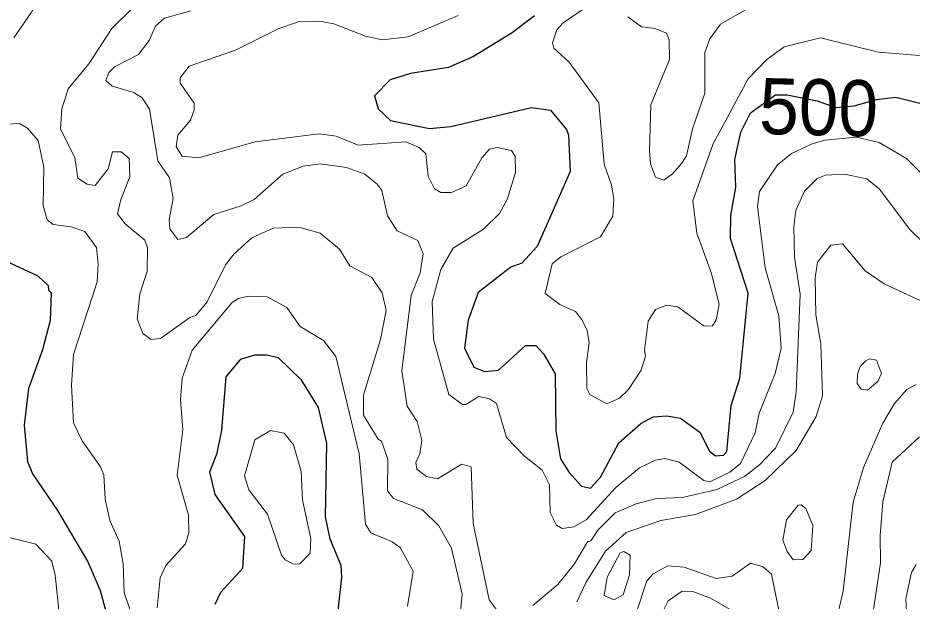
# Model space of a CAD drawing. Extents: x 763.2 to 816.8, y 7896.5 to 7952.7.
# Drawn here: x 772.72 to 775.277, y 7898.789 to 7900.455 of the extents above; entities that cross this region are included whole.
import ezdxf
from ezdxf.enums import TextEntityAlignment as Align

# ---------------------------------------------------------------- set-up
doc = ezdxf.new("R2010")
doc.units = 0
doc.header["$LTSCALE"] = 0.064
doc.layers.add('1', color=7, linetype='Continuous', lineweight=25)
doc.layers.add('2', color=7, linetype='Continuous', lineweight=13)
doc.layers.add('61', color=7, linetype='Continuous')

msp = doc.modelspace()

# ---------------------------------------------------------------- linework, layer by layer
at = {"layer": '1'}
for points in [[(774.1975, 7900.4606), (774.1333, 7900.4122), (774.0232, 7900.3441), (773.951, 7900.3128), (773.8425, 7900.2962), (773.7841, 7900.2783), (773.7397, 7900.2319), (773.7503, 7900.195), (773.7859, 7900.1619)], [(774.289, 7900.1358), (774.2944, 7900.1196), (774.2989, 7900.0156), (774.2047, 7899.8015), (774.1609, 7899.7545), (774.1299, 7899.7431), (774.0358, 7899.6704), (774.0074, 7899.5914), (773.9973, 7899.5108), (774.0238, 7899.4567), (774.0541, 7899.4448), (774.0939, 7899.4484), (774.1714, 7899.5187), (774.2007, 7899.5185), (774.2234, 7899.4946), (774.2565, 7899.4375), (774.2583, 7899.2748), (774.2716, 7899.1952), (774.2962, 7899.1558), (774.3316, 7899.1173), (774.3569, 7899.1117), (774.3862, 7899.1424), (774.4379, 7899.2409), (774.5017, 7899.2958), (774.5368, 7899.3151), (774.5755, 7899.3183), (774.6149, 7899.3116), (774.6702, 7899.2712), (774.6974, 7899.2169), (774.7145, 7899.2032), (774.7375, 7899.2057), (774.7474, 7899.216), (774.7597, 7899.347), (774.7843, 7899.426), (774.8086, 7899.6683), (774.7579, 7899.8246), (774.759, 7899.8902), (774.7726, 7899.9716), (774.7696, 7900.0505), (774.7873, 7900.1279), (774.8153, 7900.1838), (774.8864, 7900.2348), (774.9193, 7900.2352), (775.0053, 7900.218), (775.0593, 7900.1984), (775.111, 7900.2033), (775.1748, 7900.2217), (775.2301, 7900.2279), (775.2989, 7900.211)], [(773.7859, 7900.1619), (773.8968, 7900.1385), (773.9583, 7900.1446), (774.1884, 7900.1992), (774.2434, 7900.1908), (774.289, 7900.1358)], [(772.6827, 7899.7617), (772.7775, 7899.7176), (772.8064, 7899.6903), (772.8075, 7899.6768), (772.8153, 7899.6693), (772.8121, 7899.5904), (772.7904, 7899.5067)], [(772.7904, 7899.5067), (772.7508, 7899.3959), (772.7382, 7899.2912), (772.7477, 7899.187), (772.7616, 7899.1518), (772.8329, 7899.0479)], [(773.2838, 7898.7803), (773.3004, 7898.8142), (773.3628, 7898.883), (773.3686, 7898.9728), (773.284, 7899.0935), (773.2691, 7899.1578), (773.29, 7899.2109), (773.3033, 7899.2766), (773.3156, 7899.4291), (773.3578, 7899.4799), (773.3973, 7899.4926), (773.4309, 7899.4926), (773.4638, 7899.4844), (773.5286, 7899.4219), (773.5787, 7899.3413), (773.6024, 7899.2387), (773.5986, 7899.0296), (773.612, 7898.9667), (773.6437, 7898.891), (773.6452, 7898.8559), (773.6257, 7898.6775)], [(772.8329, 7899.0479), (772.9204, 7898.9009), (772.9555, 7898.8188), (772.9745, 7898.7488)]]:
    msp.add_lwpolyline(points, dxfattribs=at)
at = {"layer": '2'}
for points in [[(772.7002, 7900.9819), (772.7453, 7901.0131), (772.7791, 7901.0275), (772.8288, 7901.0213), (772.8725, 7900.9624), (772.876, 7900.916), (772.8666, 7900.84), (772.8238, 7900.6453), (772.8233, 7900.6037), (772.807, 7900.5593), (772.7594, 7900.471), (772.7082, 7900.3975)], [(774.4524, 7900.5896), (774.4245, 7900.5482), (774.3757, 7900.507), (774.2792, 7900.4404), (774.2608, 7900.4211), (774.2487, 7900.3836)], [(773.9856, 7898.7587), (773.9903, 7898.8087), (773.9602, 7898.9401), (773.9238, 7899.0033), (773.8774, 7899.0491), (773.7941, 7899.0815), (773.7769, 7899.104), (773.7783, 7899.1944), (773.7599, 7899.2459), (773.7505, 7899.2515), (773.7081, 7899.3197), (773.7079, 7899.3769), (773.7567, 7899.5364), (773.7733, 7899.6192), (773.7613, 7899.6697), (773.7324, 7899.7128), (773.6691, 7899.7468), (773.6398, 7899.7938), (773.5839, 7899.8394), (773.5237, 7899.8574), (773.4497, 7899.8538), (773.389, 7899.8261), (773.3384, 7899.7807), (773.3134, 7899.7489), (773.2615, 7899.6434), (773.2291, 7899.6044), (773.2112, 7899.599), (773.1279, 7899.5384), (773.1015, 7899.5356), (773.0772, 7899.5534), (773.0614, 7899.5948), (773.0685, 7899.6651), (773.0897, 7899.731), (773.091, 7899.798), (773.0827, 7899.82), (773.0263, 7899.8669), (773.0044, 7899.8948), (773.0142, 7899.9364), (773.0404, 7900.0005), (773.0386, 7900.0529), (773.0157, 7900.0724), (772.9901, 7900.0726), (772.9779, 7900.0235), (772.9414, 7899.9759), (772.9183, 7899.9794), (772.8914, 7899.9969), (772.8825, 7900.0563), (772.8417, 7900.1367), (772.8452, 7900.195), (772.8634, 7900.2517), (772.9226, 7900.3232), (772.9882, 7900.4242), (773.046, 7900.481)], [(773.2148, 7900.4753), (773.1397, 7900.454), (773.1139, 7900.4314), (773.0955, 7900.3902), (773.0645, 7900.35), (772.9967, 7900.3149), (772.9797, 7900.2988), (772.9716, 7900.2759), (772.9897, 7900.2601), (773.0513, 7900.2412), (773.0754, 7900.2264), (773.0961, 7900.1941), (773.12, 7900.0464), (773.1534, 7899.9977), (773.1636, 7899.9388), (773.1523, 7899.8788), (773.1541, 7899.8525), (773.1771, 7899.8218), (773.202, 7899.8272), (773.2801, 7899.8932), (773.358, 7899.9178), (773.3955, 7899.9362), (773.4777, 7900.0085), (773.5354, 7900.0313), (773.5843, 7900.0383), (773.6596, 7900.0272), (773.7116, 7900.0083), (773.7478, 7899.9801), (773.7605, 7899.9613), (773.7767, 7899.8894), (773.8048, 7899.8464), (773.864, 7899.8192), (773.8784, 7899.7809), (773.8699, 7899.7263), (773.8442, 7899.6619), (773.8179, 7899.4464), (773.8329, 7899.3459), (773.8618, 7899.3022), (773.875, 7899.2484), (773.8692, 7899.2097), (773.8576, 7899.1845)], [(774.1416, 7900.0601), (774.1312, 7900.0757), (774.0905, 7900.0841), (774.0686, 7900.0801), (774.0469, 7900.0552), (774.002, 7899.9747), (773.9601, 7899.9561), (773.9291, 7899.9563), (773.9113, 7899.9666), (773.893, 7900.0027), (773.8863, 7900.0665), (773.8675, 7900.0849), (773.8293, 7900.1006), (773.6928, 7900.0909), (773.6304, 7900.1166), (773.5813, 7900.1235), (773.3982, 7900.1004), (773.2377, 7900.0548), (773.1898, 7900.0596), (773.1722, 7900.0867), (773.1769, 7900.1196), (773.2139, 7900.1627), (773.2244, 7900.1918), (773.2239, 7900.2114), (773.1836, 7900.2681), (773.1841, 7900.2837), (773.2102, 7900.3171), (773.3426, 7900.3627), (773.464, 7900.4235), (773.5244, 7900.4442), (773.5821, 7900.4458), (773.6231, 7900.4381), (773.7139, 7900.4027), (773.7621, 7900.3919), (773.8364, 7900.401), (773.9786, 7900.4613)], [(774.799, 7900.477), (774.7291, 7900.4365), (774.6988, 7900.3948), (774.6842, 7900.3561), (774.6843, 7900.2394), (774.6493, 7900.1379), (774.6318, 7900.061), (774.6182, 7900.0401), (774.5921, 7900.0094), (774.5668, 7899.9915), (774.5428, 7900), (774.5291, 7900.0382), (774.5256, 7900.0751), (774.5295, 7900.2064), (774.5835, 7900.3358), (774.582, 7900.3924), (774.5743, 7900.4116), (774.5425, 7900.4243), (774.5036, 7900.4296), (774.4639, 7900.4581)], [(774.2487, 7900.3836), (774.2522, 7900.3687), (774.2968, 7900.3281), (774.3813, 7900.2123), (774.3964, 7900.0373), (774.4177, 7899.9774), (774.4242, 7899.9387), (774.4209, 7899.8888), (774.386, 7899.8294), (774.2726, 7899.7726), (774.2475, 7899.7524), (774.2275, 7899.6676), (774.2694, 7899.6361), (774.314, 7899.6156), (774.3328, 7899.5932), (774.3481, 7899.5613), (774.3536, 7899.5266), (774.3455, 7899.4712), (774.3472, 7899.3963), (774.3559, 7899.3791), (774.404, 7899.3523), (774.4405, 7899.368), (774.4661, 7899.3936), (774.5025, 7899.4485), (774.5147, 7899.4882), (774.5117, 7899.5049), (774.5219, 7899.5884), (774.5428, 7899.6221), (774.5756, 7899.6338), (774.6066, 7899.6292), (774.6823, 7899.5743), (774.7066, 7899.5753), (774.7168, 7899.5922), (774.7249, 7899.6356), (774.7033, 7899.725), (774.6615, 7899.8399), (774.6497, 7899.932), (774.7073, 7900.0931), (774.8078, 7900.2804), (774.8618, 7900.3361), (774.9108, 7900.3717), (775.0148, 7900.3977), (775.1804, 7900.3572), (775.2979, 7900.3472)], [(772.6672, 7900.1503), (772.7248, 7900.153), (772.7479, 7900.14), (772.7776, 7900.1048), (772.7941, 7900.0286)], [(775.3833, 7899.9315), (775.2608, 7900.053), (775.1831, 7900.0984), (775.1178, 7900.1138), (775.0273, 7900.1057), (774.9908, 7900.0954), (774.9324, 7900.067), (774.8916, 7900.0354), (774.8402, 7899.9585), (774.8353, 7899.9159), (774.8566, 7899.7408), (774.8958, 7899.6034), (774.9025, 7899.5114), (774.8853, 7899.4392), (774.8399, 7899.3259), (774.8285, 7899.2698), (774.7862, 7899.1814), (774.7554, 7899.1573), (774.699, 7899.1297), (774.681, 7899.1329), (774.6109, 7899.1856), (774.5696, 7899.1965), (774.5433, 7899.1917), (774.4974, 7899.1695), (774.4298, 7899.1134), (774.3454, 7899.021), (774.31, 7899.0009), (774.276, 7898.9964), (774.2605, 7899.0056), (774.2421, 7899.0414), (774.2404, 7899.1205), (774.2187, 7899.1624), (774.1684, 7899.2029), (774.1172, 7899.2562), (774.0883, 7899.353), (774.0687, 7899.3661), (774.0381, 7899.3727), (774.0008, 7899.3501), (773.9909, 7899.35), (773.952, 7899.3785), (773.9084, 7899.5371), (773.905, 7899.6446), (773.9291, 7899.7361), (773.9648, 7899.7966)], [(773.9648, 7899.7966), (774.0517, 7899.8517), (774.0971, 7899.8958), (774.1191, 7899.9361), (774.143, 7900.013), (774.1416, 7900.0601)], [(772.7941, 7900.0286), (772.7924, 7899.9189), (772.8037, 7899.8777), (772.8206, 7899.8643), (772.8723, 7899.8575), (772.9118, 7899.8445)], [(774.1929, 7898.7758), (774.2636, 7898.8357), (774.3113, 7898.8949), (774.3492, 7898.9581), (774.3586, 7898.9609), (774.3792, 7898.9924), (774.4276, 7899.0405), (774.4883, 7899.0669), (774.546, 7899.0816), (774.6208, 7899.085), (774.7184, 7899.1074), (774.7978, 7899.1448), (774.841, 7899.1781), (774.8864, 7899.2254), (774.9365, 7899.3286), (774.9451, 7899.3852), (774.9565, 7899.6652), (774.9404, 7899.7716), (774.9387, 7899.8584), (774.9448, 7899.9041), (774.9692, 7899.9598), (775.0051, 7899.9957), (775.0292, 7900.0052), (775.0832, 7900.0087), (775.1476, 7899.9952), (775.1835, 7899.9659), (775.2708, 7899.8505), (775.305, 7899.8165)], [(772.9118, 7899.8445), (772.9451, 7899.799), (772.9499, 7899.7513), (772.9466, 7899.7005), (772.8795, 7899.4935), (772.873, 7899.4055), (772.8795, 7899.2982), (772.9041, 7899.2467), (772.9563, 7899.1727), (772.9662, 7899.1495), (772.9699, 7899.0802), (772.9833, 7899.0186), (773.0098, 7898.9597), (773.0208, 7898.8954), (773.0243, 7898.8132), (773.0426, 7898.7573)], [(775.3021, 7899.6464), (775.1968, 7899.6948), (775.143, 7899.7321), (775.0782, 7899.8095), (775.0449, 7899.8059), (775.0063, 7899.757), (774.9996, 7899.7119), (775.0016, 7899.6063), (775.0159, 7899.5232), (775.0206, 7899.3753), (775.0023, 7899.3161), (774.9452, 7899.219), (774.8569, 7899.1334)], [(773.1179, 7898.7692), (773.1266, 7898.8547), (773.1434, 7898.8905), (773.1997, 7898.9522), (773.2086, 7898.9837), (773.208, 7899.034), (773.1755, 7899.1485), (773.1917, 7899.278), (773.1853, 7899.3646), (773.1894, 7899.426), (773.2186, 7899.506), (773.3318, 7899.6404), (773.3495, 7899.6533), (773.3793, 7899.6601), (773.4328, 7899.6582), (773.489, 7899.6273), (773.5269, 7899.5732), (773.5938, 7899.5327), (773.6291, 7899.4871), (773.696, 7899.209), (773.7136, 7899.008), (773.7295, 7898.9833), (773.7899, 7898.9583), (773.8135, 7898.9414), (773.8506, 7898.8746), (773.8341, 7898.7739)], [(775.0585, 7898.7268), (775.08, 7898.8178), (775.1082, 7899.0709), (775.1375, 7899.1706), (775.1936, 7899.297), (775.2268, 7899.3535), (775.2617, 7899.3931), (775.2883, 7899.407)], [(775.298, 7899.2576), (775.22, 7899.1852), (775.1929, 7899.0725), (775.1853, 7898.9764), (775.1867, 7898.898), (775.1623, 7898.739)], [(773.8576, 7899.1845), (773.861, 7899.1658), (773.8886, 7899.1443), (773.92, 7899.1377), (773.9899, 7899.1798), (774.0164, 7899.1719)], [(774.0164, 7899.1719), (774.0214, 7899.01), (774.0672, 7898.7921), (774.0908, 7898.7618)], [(774.8569, 7899.1334), (774.7748, 7899.0794), (774.6577, 7899.0358), (774.5584, 7899.019), (774.4589, 7898.9847), (774.4005, 7898.9317)], [(772.5945, 7898.5687), (772.7371, 7898.5429), (772.777, 7898.52), (772.8169, 7898.5134), (772.8693, 7898.5445), (772.8827, 7898.5848), (772.8859, 7898.6298), (772.8655, 7898.6964), (772.8387, 7898.7442), (772.8265, 7898.8624), (772.8167, 7898.9023), (772.7714, 7898.9516), (772.6948, 7898.9702)], [(774.4005, 7898.9317), (774.3452, 7898.8428), (774.3183, 7898.7864)], [(774.488, 7898.7541), (774.5181, 7898.8465), (774.5369, 7898.8664), (774.5789, 7898.8892), (774.6253, 7898.8859), (774.7169, 7898.8535), (774.7622, 7898.8599), (774.8152, 7898.8972), (774.8506, 7898.8865), (774.8748, 7898.8656), (774.8965, 7898.7584)], [(775.2668, 7898.6449), (775.2592, 7898.7948), (775.2755, 7898.8701), (775.2887, 7898.8928)], [(774.7816, 7898.7507), (774.7004, 7898.7974), (774.6498, 7898.8158), (774.6196, 7898.8172), (774.5791, 7898.789), (774.557, 7898.7435)]]:
    msp.add_lwpolyline(points, dxfattribs=at)
for points in [[(775.1211, 7899.4357), (775.1281, 7899.4593), (775.1448, 7899.4748), (775.1552, 7899.4811), (775.1755, 7899.4772), (775.1898, 7899.4392), (775.1789, 7899.4157), (775.1494, 7899.3908), (775.1312, 7899.3944), (775.1194, 7899.4102)], [(773.4336, 7899.0368), (773.3808, 7899.1065), (773.3677, 7899.1468), (773.3973, 7899.249), (773.4422, 7899.2756), (773.4814, 7899.2687), (773.508, 7899.2354), (773.5301, 7899.159), (773.5335, 7899.0775), (773.5581, 7898.9665), (773.5554, 7898.9258), (773.5266, 7898.8947), (773.508, 7898.8944), (773.4844, 7898.9065), (773.4741, 7898.9202)], [(774.9178, 7899.0212), (774.9509, 7899.0625), (774.9594, 7899.0635), (774.9732, 7899.053), (774.9928, 7899.0044), (774.9882, 7898.9333), (774.9648, 7898.9078), (774.9373, 7898.9063), (774.92, 7898.9302), (774.9076, 7898.9626)], [(774.4689, 7898.8636), (774.4703, 7898.92), (774.4527, 7898.9302), (774.4425, 7898.9268), (774.4048, 7898.8573), (774.396, 7898.8046), (774.4245, 7898.7925), (774.4505, 7898.8064)]]:
    msp.add_lwpolyline(points, close=True, dxfattribs=at)

# ---------------------------------------------------------------- texts
at = {"layer": '61', "width": 0.95}
msp.add_text('500', height=0.16, rotation=358.69, dxfattribs=at).set_placement((775.008, 7900.1196), align=Align.CENTER)

doc.saveas('drawing.dxf')
